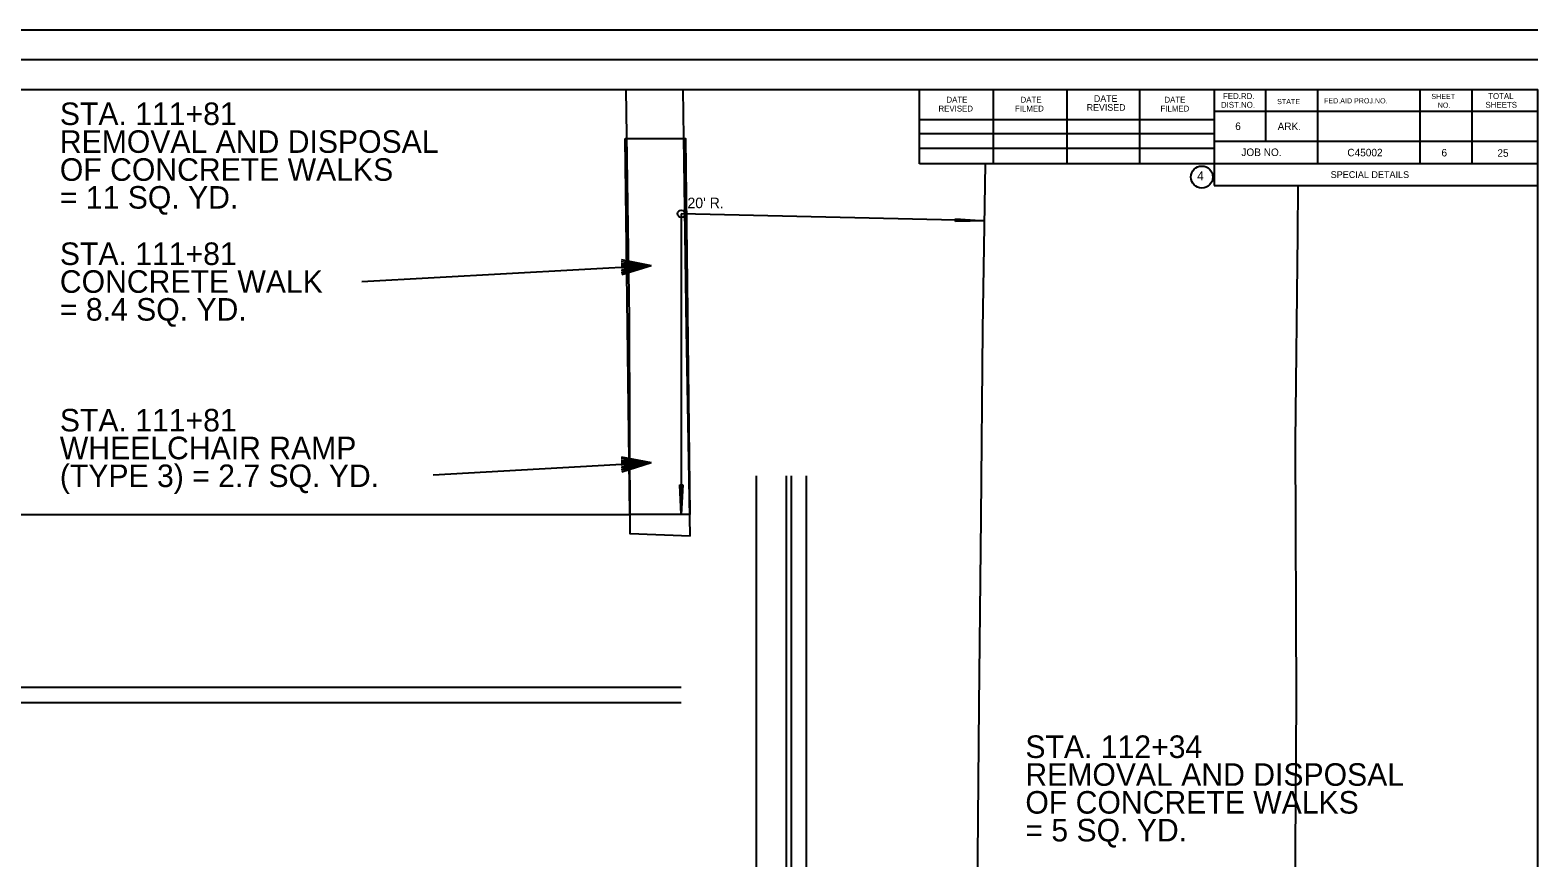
# Model space of a CAD drawing. Extents: x 1944905 to 1956777, y 763871 to 764977.
# Drawn here: x 1948938 to 1949941, y 764426 to 764977 of the extents above; entities that cross this region are included whole.
import ezdxf

# ---------------------------------------------------------------- set-up
doc = ezdxf.new("R2010")
doc.units = 0
for name, color, linetype in [('A_Sidewalk', 7, 'Continuous'), ('Default', 7, 'Continuous'), ('R_Horz Alg', 7, 'Continuous'), ('S_CROSS_DRAIN', 7, 'Continuous'), ('S_EDGE_PAVEMENT', 7, 'Continuous')]:
    doc.layers.add(name, color=color, linetype=linetype)

msp = doc.modelspace()

# ---------------------------------------------------------------- linework, layer by layer
at = {"layer": 'A_Sidewalk'}
msp.add_lwpolyline([(1949333.9, 764904.6), (1949373.9, 764904.6), (1949376.9, 764654.6), (1949371.2, 764654.6), (1949336.9, 764654.6)], close=True, dxfattribs=at)
at = {"layer": 'Default'}
for p, q in [((1949941, 764976.7), (1948322.3, 764976.7)), ((1949941, 764957), (1948322.3, 764957)), ((1948360.1, 764937.3), (1949941, 764937.3)), ((1949529.7, 764887.9), (1949529.7, 764937.3)), ((1949579, 764887.9), (1949579, 764936.3)), ((1949627.9, 764887.9), (1949627.9, 764936.3)), ((1949676.2, 764887.9), (1949676.2, 764936.3)), ((1949725.6, 764937.3), (1949725.6, 764873.3)), ((1949759.8, 764937.3), (1949759.8, 764902.6)), ((1949794.5, 764937.3), (1949794.5, 764887.9)), ((1949862.4, 764937.3), (1949862.4, 764887.9)), ((1949897, 764937.3), (1949897, 764887.9)), ((1949941, 763910.1), (1949941, 764937.3)), ((1949529.7, 764917.3), (1949725.6, 764917.3)), ((1949941, 764922.6), (1949725.6, 764922.6)), ((1949529.7, 764908), (1949725.6, 764908)), ((1949529.7, 764898.2), (1949725.6, 764898.2)), ((1949941, 764902.6), (1949725.6, 764902.6)), ((1949941, 764887.9), (1949529.7, 764887.9)), ((1949725.6, 764873.3), (1949941, 764873.3)), ((1949573.1, 764849.9), (1949371.2, 764854.6)), ((1949371.2, 764854.6), (1949371.2, 764654.6)), ((1949553.6, 764851.3), (1949573.1, 764849.9)), ((1949553.6, 764849.4), (1949553.6, 764851.3)), ((1949553.6, 764851.3), (1949553.6, 764851.3)), ((1949573.1, 764849.9), (1949553.6, 764849.4)), ((1949331.1, 764824.1), (1949351.1, 764820.2)), ((1949158.7, 764809.5), (1949351.1, 764820.2)), ((1949331.1, 764822.8), (1949351.1, 764820.2)), ((1949331.1, 764819), (1949351.1, 764820.2)), ((1949331.2, 764821.6), (1949351.1, 764820.2)), ((1949331.3, 764820.3), (1949351.1, 764820.2)), ((1949331.4, 764817.8), (1949351.1, 764820.2)), ((1949331.5, 764816.6), (1949351.1, 764820.2)), ((1949331.5, 764815.3), (1949351.1, 764820.2)), ((1949331.6, 764814.1), (1949351.1, 764820.2)), ((1949331.1, 764693), (1949351.1, 764689.1)), ((1949206.1, 764681), (1949351.1, 764689.1)), ((1949331.1, 764691.7), (1949351.1, 764689.1)), ((1949331.1, 764688), (1949351.1, 764689.1)), ((1949331.2, 764690.5), (1949351.1, 764689.1)), ((1949331.3, 764689.2), (1949351.1, 764689.1)), ((1949331.4, 764686.7), (1949351.1, 764689.1)), ((1949331.5, 764685.5), (1949351.1, 764689.1)), ((1949331.5, 764684.2), (1949351.1, 764689.1)), ((1949331.6, 764683), (1949351.1, 764689.1)), ((1949371.2, 764654.6), (1949370.2, 764674.2)), ((1949370.2, 764674.2), (1949372.2, 764674.2)), ((1949372.2, 764674.2), (1949371.2, 764654.6)), ((1949372.2, 764674.2), (1949372.2, 764674.2))]:
    msp.add_line(p, q, dxfattribs=at)
for points in [[(1949377, 764640.2), (1949337.2, 764641.6), (1949336.8, 764785), (1949334.5, 764937.3)], [(1949377, 764640.2), (1949374.6, 764777.5), (1949372.4, 764937.3)]]:
    msp.add_lwpolyline(points, dxfattribs=at)
for centre, radius in [((1949717.5, 764879), 7.33), ((1949371.2, 764854.6), 2.44)]:
    msp.add_circle(centre, radius, dxfattribs=at)
at = {"layer": 'R_Horz Alg'}
for p, q in [((1948371.2, 764654.6), (1949337, 764654.6)), ((1948371.2, 764539.6), (1949371.2, 764539.6)), ((1948371.2, 764529.6), (1949371.2, 764529.6))]:
    msp.add_line(p, q, dxfattribs=at)
at = {"layer": 'S_CROSS_DRAIN'}
for p, q in [((1949421.3, 764388.2), (1949421.3, 764680.3)), ((1949441.3, 764388.2), (1949441.3, 764680.3)), ((1949444.5, 764390.4), (1949444.5, 764680.3)), ((1949454.5, 764390.4), (1949454.5, 764680.3))]:
    msp.add_line(p, q, dxfattribs=at)
at = {"layer": 'S_EDGE_PAVEMENT'}
for points in [[(1949563.8, 764022.9), (1949564.7, 764098.5), (1949567, 764277), (1949568.2, 764402.1), (1949569.4, 764527.3), (1949570.7, 764652.5), (1949571.9, 764777.7), (1949573.5, 764887.9)], [(1949773.6, 763910.1), (1949776, 764080.3), (1949778.5, 764267.6), (1949779.5, 764399.3), (1949780.5, 764531), (1949779.9, 764703), (1949781.3, 764840.6), (1949781.6, 764873.3)]]:
    msp.add_lwpolyline(points, dxfattribs=at)

# ---------------------------------------------------------------- texts
at = {"layer": 'Default'}
for s, height, p in [('DATE', 4.4, (1949645.7, 764929)), ('FED.RD.', 3.91, (1949731.6, 764930.9)), ('SHEET', 3.42, (1949870.2, 764930.9)), ('TOTAL', 3.91, (1949908, 764930.9)), ('STA. 111+81', 15, (1948957.8, 764913.6)), ('REVISED', 3.91, (1949542.3, 764922.6)), ('DATE', 3.91, (1949547.6, 764928.5)), ('FILMED', 3.91, (1949593.2, 764922.6)), ('DATE', 3.91, (1949596.9, 764928.5)), ('REVISED', 4.4, (1949640.9, 764923.1)), ('FILMED', 3.91, (1949690, 764922.6)), ('DATE', 3.91, (1949692.6, 764928.5)), ('DIST.NO.', 3.91, (1949730.2, 764925.1)), ('STATE', 3.42, (1949767.6, 764927.5)), ('FED.AID PROJ.NO.', 3.42, (1949798.8, 764928)), ('NO.', 3.42, (1949874.4, 764925.1)), ('SHEETS', 3.91, (1949906.2, 764925.1)), ('6', 5, (1949739.7, 764910.3)), ('ARK.', 5, (1949767.9, 764910.2)), ('REMOVAL AND DISPOSAL', 15, (1948957.8, 764895.1)), ('JOB NO.', 5, (1949743.8, 764893)), ('C45002', 5, (1949814.3, 764892.8)), ('6', 5, (1949876.9, 764892.7)), ('25', 5, (1949914.1, 764892.5)), ('OF CONCRETE WALKS', 15, (1948957.8, 764876.5)), ('= 11 SQ. YD.', 15, (1948957.8, 764858)), ('4', 5.86, (1949714.4, 764876.9)), ('SPECIAL DETAILS', 4.5, (1949803.2, 764878.4)), ("20' R.", 7, (1949375.3, 764858.3)), ('STA. 111+81', 15, (1948957.8, 764820.5)), ('CONCRETE WALK', 15, (1948957.8, 764802)), ('= 8.4 SQ. YD.', 15, (1948957.8, 764783.5)), ('STA. 111+81', 15, (1948957.8, 764709.8)), ('WHEELCHAIR RAMP', 15, (1948957.8, 764691.3)), ('(TYPE 3) = 2.7 SQ. YD.', 15, (1948957.8, 764672.8)), ('STA. 112+34', 15, (1949600.1, 764492.6)), ('REMOVAL AND DISPOSAL', 15, (1949600.1, 764474.1)), ('OF CONCRETE WALKS', 15, (1949600.1, 764455.6)), ('= 5 SQ. YD.', 15, (1949600.1, 764437.1))]:
    msp.add_text(s, height=height, dxfattribs=at).set_placement(p)

doc.saveas('drawing.dxf')
